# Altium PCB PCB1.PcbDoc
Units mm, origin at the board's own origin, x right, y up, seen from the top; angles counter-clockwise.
Board outline 160 x 100 mm, 4 copper layers (Top Signal, GND, Power Plane, Bottom Signal), stack 1.538 mm thick; 136 components, 81 nets, 446 pads, 114 vias.
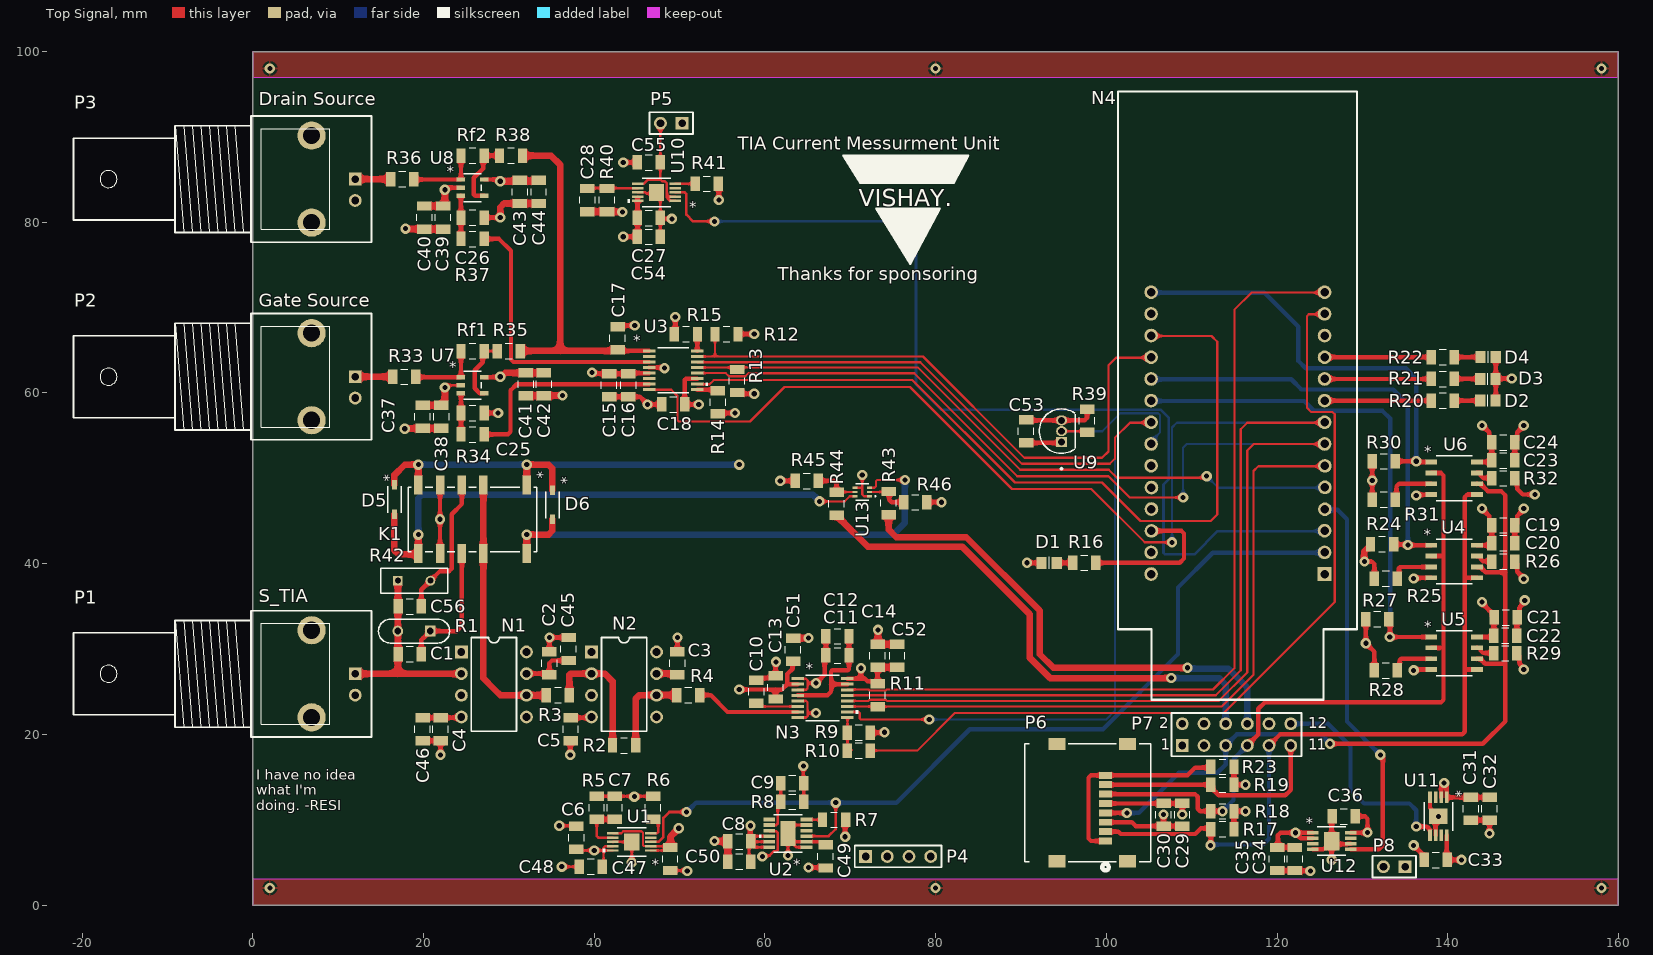
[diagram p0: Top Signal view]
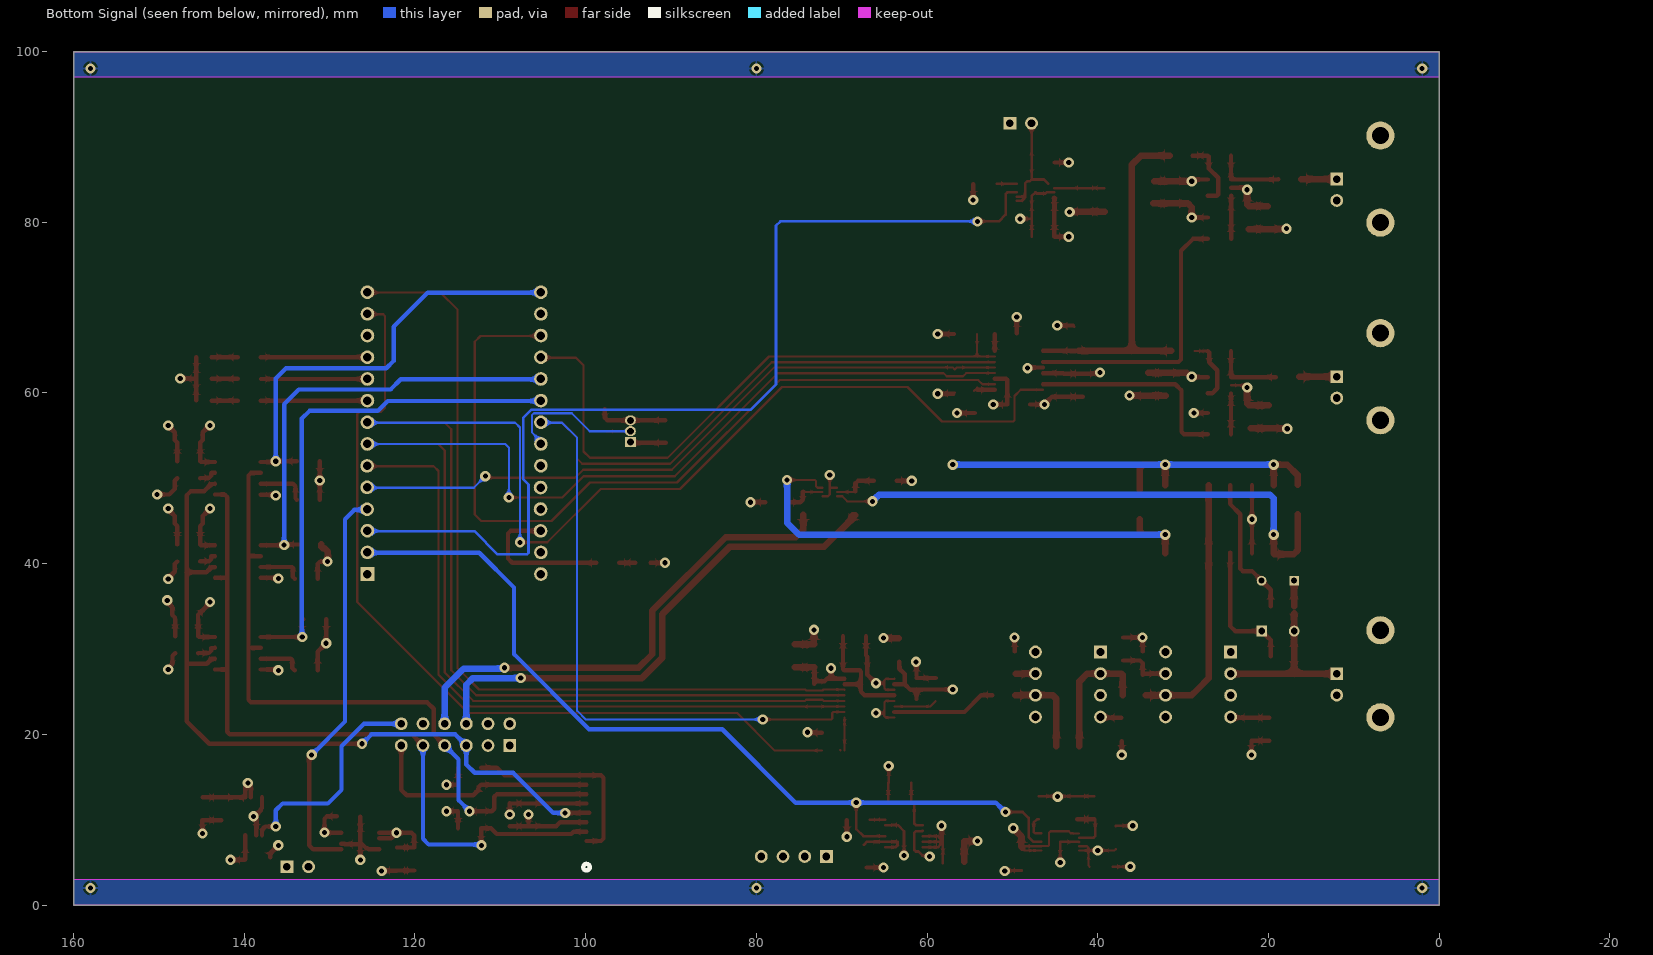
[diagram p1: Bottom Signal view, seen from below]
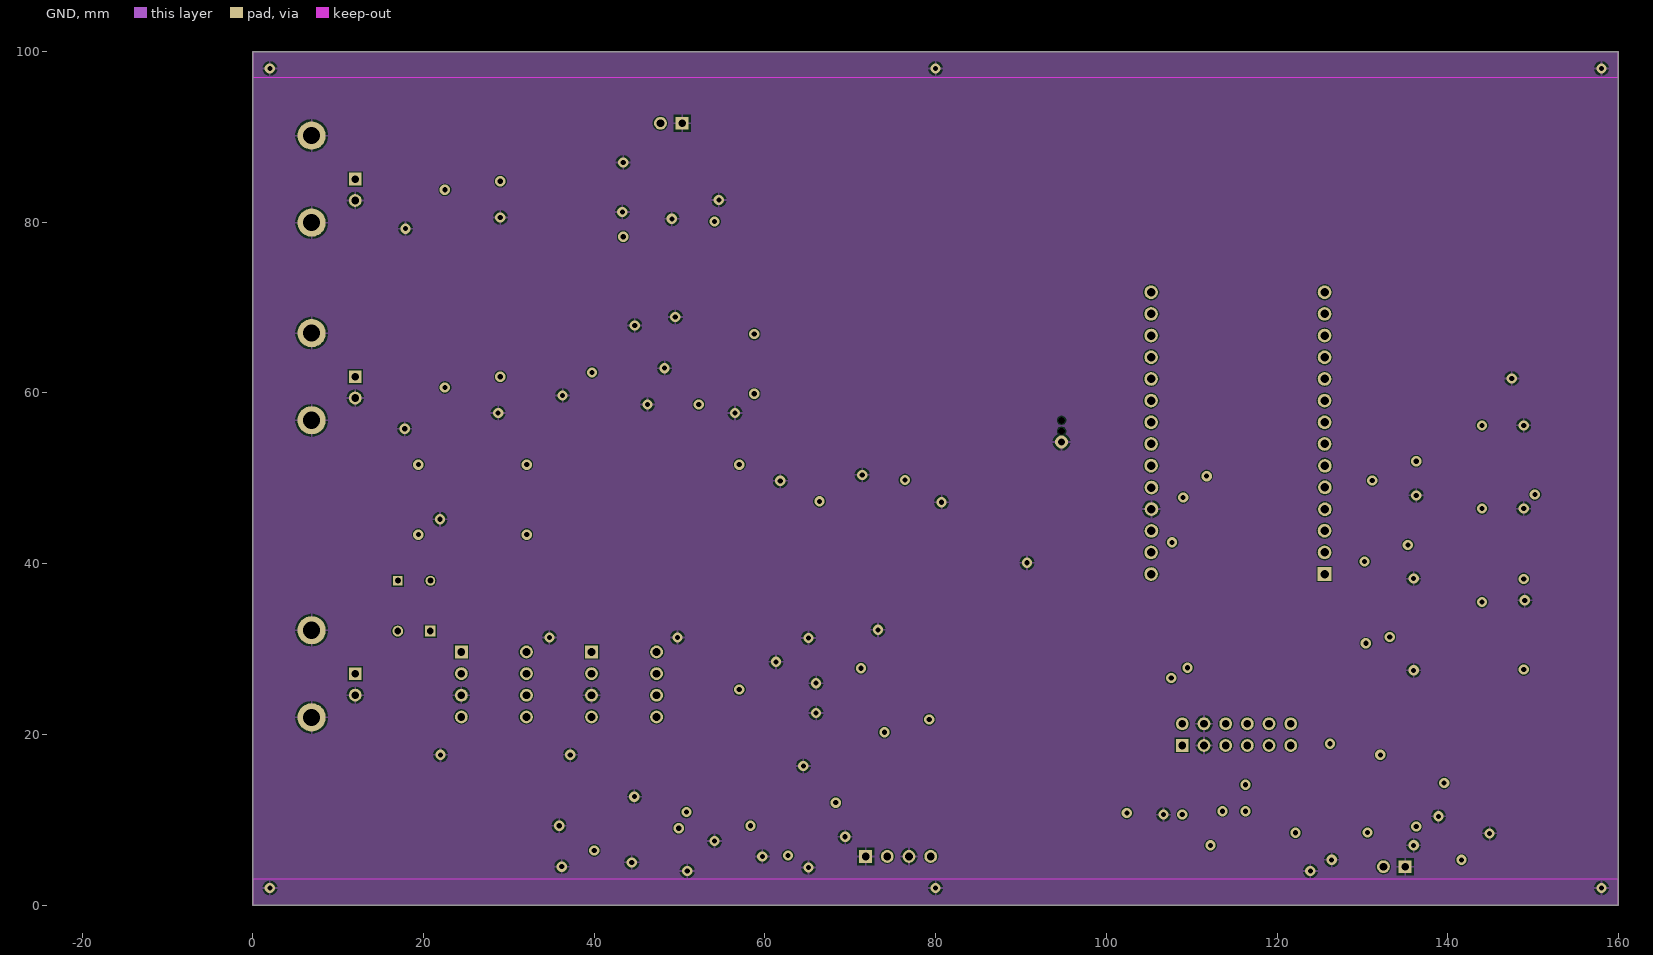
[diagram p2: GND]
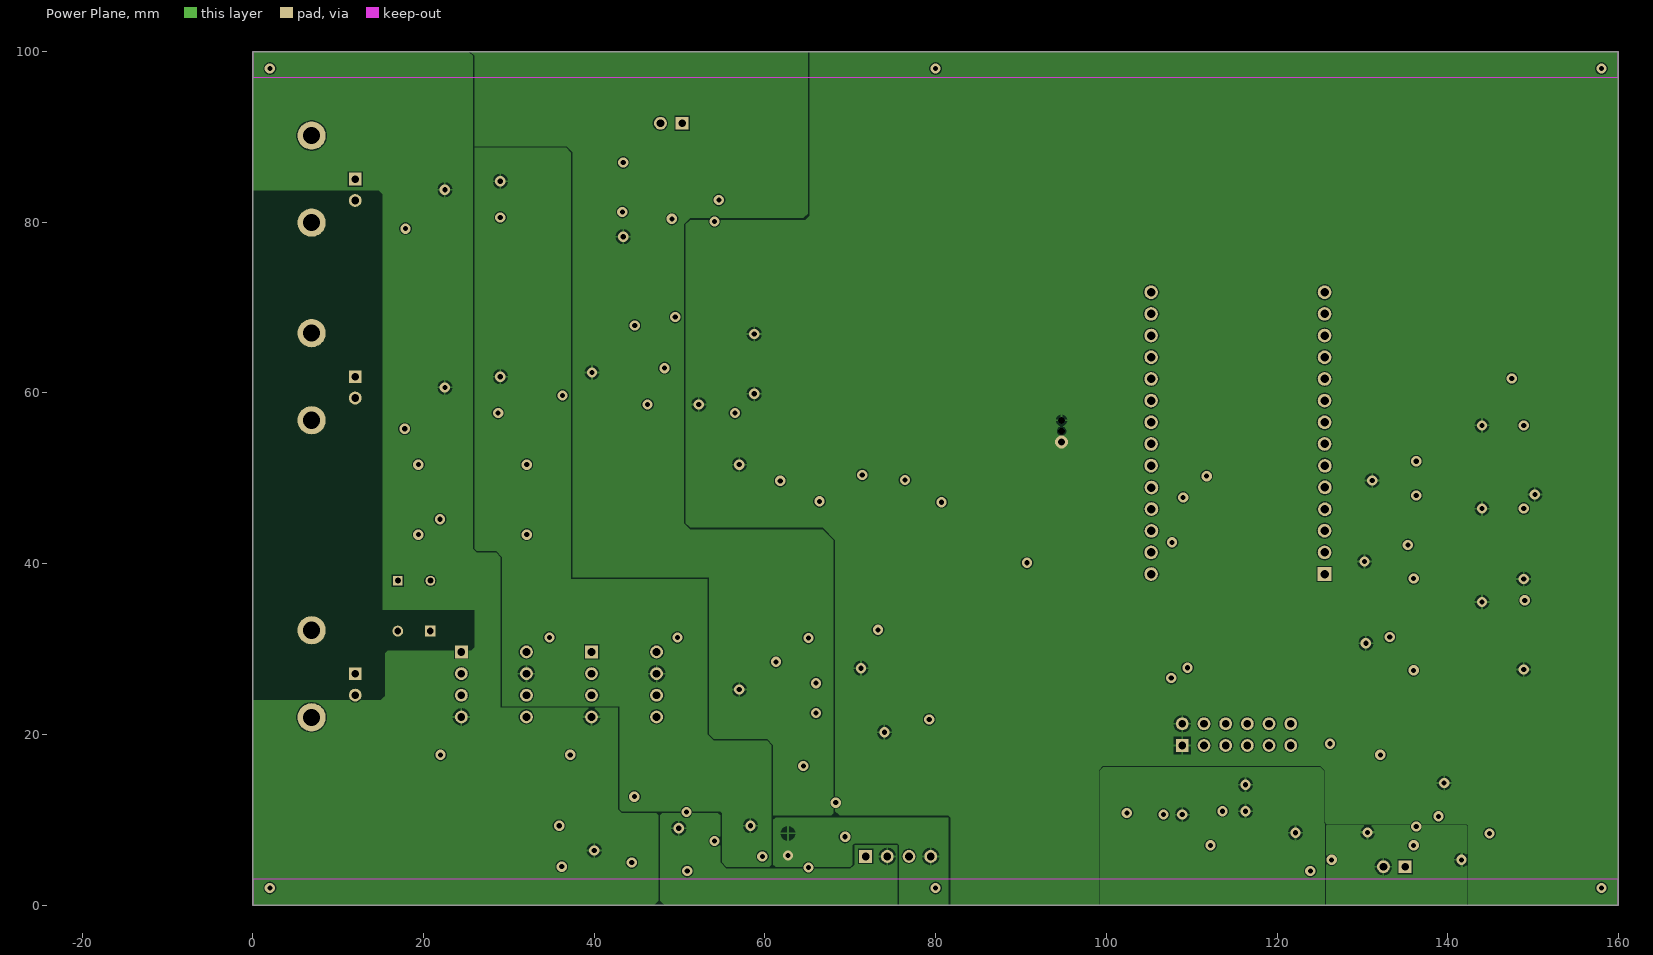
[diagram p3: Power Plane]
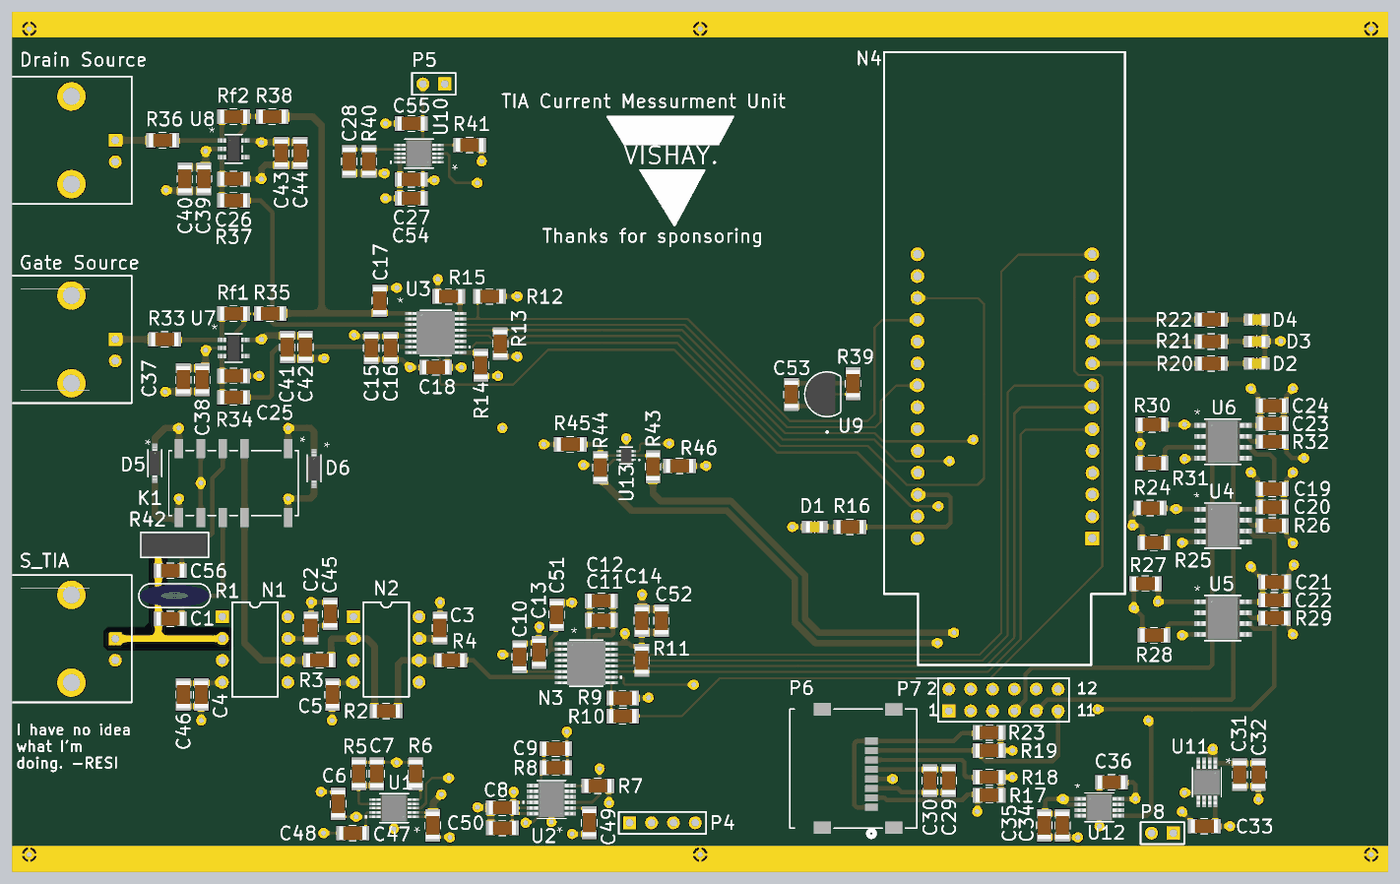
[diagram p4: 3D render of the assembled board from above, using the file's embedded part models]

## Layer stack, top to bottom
Top Solder: solder mask 0.0102, Solder Resist, Dk 3.5
Top Signal: signal copper 0.0356
Dielectric 4: prepreg 0.1524, PP-006, Dk 4.4
GND: signal copper 0.035
Dielectric 1: dielectric 1.0922, FR-4, Dk 4.8
Power Plane: signal copper 0.035
Dielectric 5: prepreg 0.1524, PP-006, Dk 4.4
Bottom Signal: signal copper 0.0356
Bottom Solder: solder mask 0.0102, Solder Resist, Dk 3.5

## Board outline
0,0 160,0 160,100 0,100

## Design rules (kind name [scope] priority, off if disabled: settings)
Clearance [All] p1: gap=0.127 ignorepadtopadclearanceinfootprint=TRUE except(0.025: THPad-THPad)
MinimumSolderMaskSliver THT_21-0248A_Q3-1_MXM [HasFootprint('21-0248A_Q3-1_MXM')] p1: minsoldermaskwidth=0
MinimumSolderMaskSliver [All] p2: minsoldermaskwidth=0.127
PolygonConnect [All] p1: connectstyle=Relief reliefconductorwidth=0.254 reliefentries=4 polygonreliefangle="90 Angle" airgapwidth=0.254
RoutingVias [All] p1: holewidth=0.6 width=1.2 viastyle="Through Hole" minholewidth=0.3 minwidth=0.6 maxholewidth=1 maxwidth=2
SilkToSolderMaskClearance SilkToSolderMaskClearance_1 [HasFootprint('BNC_RA CON')] p1: minsilkscreentomaskgap=0 clearancetoexposedcopper=TRUE
SilkToSolderMaskClearance [IsPad] p2: minsilkscreentomaskgap=0.127 clearancetoexposedcopper=TRUE
SolderMaskExpansion [All] p1: expansion=0.102 istentingtop=FALSE
Width Source [InNet('M_source')] p1: maxlimit=2.54 minlimit=0.254 preferedwidth=0.762
Width Width_1 [All] p2: maxlimit=0.762 minlimit=0.254 preferedwidth=0.762
28 further rules are at their usual default settings.

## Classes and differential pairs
component class U_Digital_Psu: C31 C32 C33 C34 C35 C36 U11 U12
component class U_Analog_PSU_5: C27 C28 C54 R40 R41 U10
component class U_Temp_Sensors: C53 R39 U9
component class U_Source_TIA: C1 C2 C3 C4 C5 C45 C46 C56 D5 D6 K1 N1 N2 R1 R2 R3 R4 R42
component class U_PSRAM_SPI: C19 C20 C21 C22 C23 C24 R24 R25 R26 R27 R28 R29 R30 R31 R32 U4 U5 U6
component class U_OPV_psu: C6 C7 C8 C9 C47 C48 C49 C50 R5 R6 R7 R8 U2
component class U_DAC_Buffer_Filter: C25 C26 C37 C38 C39 C40 C41 C42 C43 C44 R33 R34 R35 R36 R37 R38 Rf1 Rf2 U7 U8
component class U_CortexM3_dev: C29 C30 D1 D2 D3 D4 N4 P6 P7 R16 R17 R18 R19 R20 R21 R22 R23
component class U_ADC_8681: C10 C11 C12 C13 C14 C51 C52 N3 R9 R10 R11
component class U_AD_5689_DAC: C15 C16 C17 C18 R12 R13 R14 R15 U3
component class Top_Sheet: C55 P1 P2 P3 P4 P5 P8 R43 R44 R45 R46 U13

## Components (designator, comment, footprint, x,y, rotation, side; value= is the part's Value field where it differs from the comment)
C1 "22pF" C1206-KUE 18.4,29.4 r0 top
C2 "100nF" C1206-KUE 34.75,28.35 r270 top
C3 "100nF" C1206-KUE 49.75,28.35 r270 top
C4 "100nF" C1206-KUE 22,20.6 r90 top
C5 "100nF" C1206-KUE 37.25,20.6 r90 top
C6 "10uF" C1206-KUE 37.907,7.9 r270 top
C7 "4.7uF" C1206-KUE 42.407,11.4 r270 top
C8 "10uF" C1206-KUE 57,7.451 r0 top
C9 "4.7uF" C1206-KUE 63.2,14.3 r180 top
C10 "10uF" C1206-KUE 59,25 r270 top
C11 "100nF" C1206-KUE 68.5,29.25 r0 top
C12 "10uF" C1206-KUE 68.5,31.5 r0 top
C13 "0.1uF" C1206-KUE 61.25,25.5 r270 top
C14 "0.1uF" C1206-KUE 73.2,29.2 r270 top
C15 "10uF" C1206-KUE 41.75,60.9 r90 top
C16 "0.1uF" C1206-KUE 44,60.9 r90 top
C17 "0.1uF" C1206-KUE 42.75,66.4 r270 top
C18 "0.1uF" C1206-KUE 49.25,58.65 r0 top
C19 "1uF" C1206-KUE 146.5,44.5 r180 top
C20 "100nF" C1206-KUE 146.5,42.4 r180 top
C21 "1uF" C1206-KUE 146.775,33.7 r180 top
C22 "100nF" C1206-KUE 146.75,31.575 r180 top
C23 "1uF" C1206-KUE 146.5,52.1 r180 top
C24 "100nF" C1206-KUE 146.5,54.2 r180 top
C25 "1uF" C1206-KUE 25.75,57.65 r180 top
C26 "1uF" C1206-KUE 25.75,80.55 r180 top
C27 "10uF" C1206-KUE 46.4,80.5 r180 top
C28 "4.7uF" C1206-KUE 39.2,82.6 r90 top
C29 "100nF" C1206-KUE 108.9,10.6 r90 top
C30 "1uF" C1206-KUE 106.7,10.6 r90 top
C31 "100nF" C1206-KUE 142.7,11.3 r90 top
C32 "10uF" C1206-KUE 144.9,11.3 r90 top
C33 "10uF" C1206-KUE 138.6,5.3 r0 top
C34 "100nF" C1206-KUE 122.1,5.4 r90 top
C35 "10uF" C1206-KUE 120,5.4 r90 top
C36 "4.7uF" C1206-KUE 127.8,10.4 r0 top
C37 "100nF" C1206-KUE 19.9,57.2 r90 top
C38 "1uF" C1206-KUE 22.1,57.2 r90 top
C39 "100nF" C1206-KUE 22.3,80.55 r90 top
C40 "1uF" C1206-KUE 20.1,80.55 r90 top
C41 "100nF" C1206-KUE 32,61 r90 top
C42 "1uF" C1206-KUE 34.1,61 r90 top
C43 "100nF" C1206-KUE 31.3,83.55 r90 top
C44 "1uF" C1206-KUE 33.5,83.55 r90 top
C45 "10uF" C1206-KUE 37,30 r270 top
C46 "10uF" C1206-KUE 19.9,20.6 r270 top
C47 "10uF" C1206-KUE 48.907,5.4 r90 top
C48 "100nF" C1206-KUE 39.607,4.5 r0 top
C49 "10uF" C1206-KUE 67.1,5.7 r90 top
C50 "100nF" C1206-KUE 57,5.1 r0 top
C51 "10uF" C1206-KUE 63.3,29.9 r270 top
C52 "10uF" C1206-KUE 75.5,29.2 r270 top
C53 "1uF" C1206-KUE 90.6,55.5 r90 top
C54 "100nF" C1206-KUE 46.4,78.3 r180 top
C55 "100nF" C1206-KUE 46.4,87 r0 top
C56 "22pF" C1206-KUE 18.4,35 r0 top
D1 "GREEN" 6-0805_N-KUE 93.3,40.1 r180 top
D2 "GREEN" 6-0805_N-KUE 144.7,59.1 r0 top
D3 "RED" 6-0805_N-KUE 144.7,61.65 r0 top
D4 "RED" 6-0805_N-KUE 144.725,64.2 r0 top
D5 "1N4148W-7" SOD123_DIO 16.6,47.5 r270 top
D6 "1N4148W-7" SOD123_DIO 35.1,46.9 r270 top
K1 "G6SK-2F-TR DC3" "RELAY_G6SK-2F DC3_OMR" 19.4,41.2 r270 top
N1 "LMC6001AIN/NOPB" DIP8 28.25,25.85 r270 top
N2 "LMC6001AIN/NOPB" DIP8 43.5,25.85 r270 top
N3 "ADS8681IPW" PW16_TEX 66.75,24.25 r0 top
N4 "STM32F103" DIP28 129.375,24.05 r180 top
P1 "BNC" "BNC_RA CON" 12,27.1 r0 top
P2 "BNC" "BNC_RA CON" 12,61.9 r0 top
P3 "BNC" "BNC_RA CON" 12,85.05 r0 top
P4 "Header 4" HDR1X4 71.8,5.7 r0 top
P5 "Header 2" HDR1X2 50.3,91.6 r180 top
P6 "472192001" CONN_47219-2001_MOL 97.8,12 r90 top
P7 "Header 6X2" HDR2X6 108.9,18.7 r0 top
P8 "Header 2" HDR1X2 135,4.5 r180 top
R1 "CNS020-10MP" RES_CNS020_VIS 20.8,32.1 r180 top
R2 "10k" C1206-KUE 43.5,18.7 r180 top
R3 "33k" C1206-KUE 35.75,24.6 r180 top
R4 "10" C1206-KUE 51,24.6 r180 top
R5 "78.7k" C1206-KUE 40.3,11.4 r90 top
R6 "0" C1206-KUE 46.907,11.4 r90 top
R7 "0" C1206-KUE 68.1,10 r0 top
R8 "78.7k" C1206-KUE 63.2,12.1 r0 top
R9 "10k" C1206-KUE 71,20.2 r180 top
R10 "1k" C1206-KUE 71,18.1 r180 top
R11 "4.7k" C1206-KUE 73.2,24.6 r270 top
R12 "4.7k" C1206-KUE 55.5,66.9 r180 top
R13 "4.7k" C1206-KUE 56.75,61.4 r90 top
R14 "10k" C1206-KUE 54.5,58.9 r270 top
R15 "10k" C1206-KUE 50.75,66.9 r180 top
R16 "3.9k" C1206-KUE 97.4,40.1 r180 top
R17 "4.7k" C1206-KUE 113.6,8.9 r180 top
R18 "4.7k" C1206-KUE 113.6,11 r180 top
R19 "4.7k" C1206-KUE 113.6,14.1 r180 top
R20 "3.9k" C1206-KUE 139.4,59.1 r0 top
R21 "2.7k" C1206-KUE 139.4,61.65 r0 top
R22 "2.7k" C1206-KUE 139.4,64.2 r0 top
R23 "4.7k" C1206-KUE 113.6,16.2 r0 top
R24 "4.7k" C1206-KUE 132.3,42.3 r0 top
R25 "10k" C1206-KUE 132.75,38.25 r0 top
R26 "10k" C1206-KUE 146.5,40.25 r180 top
R27 "4.7k" C1206-KUE 131.75,33.5 r0 top
R28 "10k" C1206-KUE 132.75,27.5 r0 top
R29 "10k" C1206-KUE 146.75,29.5 r180 top
R30 "4.7k" C1206-KUE 132.5,52 r0 top
R31 "10k" C1206-KUE 132.5,47.5 r0 top
R32 "10k" C1206-KUE 146.5,50 r180 top
R33 "100" C1206-KUE 17.75,61.9 r180 top
R34 "10k" C1206-KUE 25.75,55.15 r180 top
R35 "10k" C1206-KUE 30,64.9 r180 top
R36 "100" C1206-KUE 17.5,85.05 r180 top
R37 "10k" C1206-KUE 25.75,78.05 r180 top
R38 "10k" C1206-KUE 30.25,87.8 r180 top
R39 "4.7k" C1206-KUE 97.75,56.75 r270 top
R40 "49.9k" C1206-KUE 41.5,82.6 r270 top
R41 "0" C1206-KUE 53.2,84.5 r0 top
R42 "Y0062100K000T9L" RES_S102K_7P62X2P67_VIS 17,38 r0 top
R43 "1k" C1206-KUE 74.5,47.1 r270 top
R44 "1k" C1206-KUE 68.4,47 r270 top
R45 "10k" C1206-KUE 64.9,49.7 r180 top
R46 "10k" C1206-KUE 77.6,47.2 r0 top
Rf1 "20k" C1206-KUE 25.75,64.9 r180 top
Rf2 "20k" C1206-KUE 25.75,87.8 r180 top
U1 "LT3042EMSE#TRPBF" 05-08-1664_ADI 44.407,7.4 r180 top
U2 "LT3094EMSE#TRPBF" MSE_05-08-1666_ADI 62.7,8.4 r180 top
U3 "AD5689RBRUZ" RU_16_ADI 49.25,62.65 r0 top
U4 "APS6404L-3SQR-SN" APS6404L-3SQR-SN_APY 140.75,40.25 r0 top
U5 "APS6404L-3SQR-SN" APS6404L-3SQR-SN_APY 140.75,29.5 r0 top
U6 "APS6404L-3SQR-SN" APS6404L-3SQR-SN_APY 140.75,50 r0 top
U7 "OPA197IDBVR" DBV5_TEX 25.75,60.9 r0 top
U8 "OPA197IDBVR" DBV5_TEX 25.75,84.05 r0 top
U9 "DS18B20+" 21-0248A_Q3-1_MXM 94.75,54.25 r90 top
U10 "LT3042EMSE#TRPBF" 05-08-1664_ADI 47.3,83.5 r180 top
U11 "TLV76733DGNR" VSSOP8_DGN_TEX 138.9,10.4 r270 top
U12 "TLV76733DGNR" VSSOP8_DGN_TEX 126.4,7.5 r0 top
U13 "DMC2400UV-7" SON_400UV-7_DIO 71.4,48.4 r180 top

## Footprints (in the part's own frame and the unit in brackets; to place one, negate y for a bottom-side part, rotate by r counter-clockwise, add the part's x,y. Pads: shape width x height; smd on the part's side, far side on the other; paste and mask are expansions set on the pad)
05-08-1664_ADI [mil]
  rect 52.28x11 smd paste+0 mask+0: 1(-87.14,39.37) 2(-87.14,19.69) 3(-87.14,0) 4(-87.14,-19.68) 5(-87.14,-39.37) 6(87.14,-39.37) 7(87.14,-19.68) 8(87.14,0) 9(87.14,19.69) 10(87.14,39.37)
  rect 70x78 smd paste+0 mask+0: 11(0,0)
  silkscreen extent -66,-66 133,66, body extent -99,-61 99,61, height 43
6-0805_N-KUE [mm] "Chip Resistor, Body 2.0x1.2mm, IPC Medium Density"
  rect 1.2x1.4 smd: 1(-0.9,0) 2(0.9,0)
  silkscreen extent 0,-0.69 0,0.69, body extent -1,-0.63 1,0.63, height 0.8
21-0248A_Q3-1_MXM [mm]
  rect 1.168x1.27 / inner round 1.524 / far side rect 1.168x1.27 hole 0.8 paste-0.635 mask+0: 1(0,0)
  oval 1.168x1.27 / inner round 0 / far side oval 1.168x1.27 hole 0.8 paste-0.635 mask+0: 2(1.27,0) 3(2.54,0)
  silkscreen extent -3.24,-1.59 3.87,2.6, body extent -1.21,-0.95 3.75,2.48, height 4.95
APS6404L-3SQR-SN_APY [mm]
  rect 1.356x0.558 smd paste+0 mask+0: 1(-2.672,1.905) 2(-2.672,0.635) 3(-2.672,-0.635) 4(-2.672,-1.905) 5(2.672,-1.905) 6(2.672,-0.635) 7(2.672,0.635) 8(2.672,1.905)
  silkscreen extent -2.12,-2.63 2.12,2.63, body extent -3,-2.5 3,2.5, height 1.76
"BNC_RA CON" [mm] "Connector; BNC Elbow"
  rect 1.5x1.5 hole 0.9: 1(0,0)
  round 3.3 hole 2: 2(-5.1,-5.1) 2(-5.1,5.1)
  round 1.5 hole 0.9: 2(0,-2.5)
  silkscreen extent -33,-7.4 1.9,7.4
C1206-KUE [mm] "Chip Capacitor, Body 3.2x1.6mm, IPC High Density"
  rect 1.1x1.7 smd: 1(-1.35,0) 2(1.35,0)
  silkscreen extent -0.4,-0.9 0.4,0.9, body extent -1.6,-0.8 1.6,0.8, height 0.95
CONN_47219-2001_MOL [mil]
  rect 32x59 smd paste+0 mask+0: 1(126.18,-82.61) 2(82.87,-82.61) 3(39.57,-82.61) 4(-3.74,-82.61) 5(-47.05,-82.61) 6(-90.35,-82.61) 7(-133.66,-82.61) 8(-176.97,-82.61)
  rect 57x79 smd paste-39.5 mask-39.5: G1(270.67,-184.97) G2(270.67,141.8) G3(-270.67,141.8) G4(-270.67,-184.97)
  silkscreen extent -312,-290 272,290
DBV5_TEX [mil]
  rect 38.5x20 smd paste+0 mask+0: 1(-53.75,37.4) 2(-53.75,0) 3(-53.75,-37.4) 4(53.75,-37.4) 5(53.75,37.4)
  silkscreen extent -40,-65 39,65, body extent -59,-60 59,60, height 57
DIP8 [mm] "DIP; 8 Leads; Row Spacing 7.62 mm; Pitch 2.54 mm"
  rect 1.5x1.5 hole 0.9: 1(-3.81,-3.81)
  round 1.5 hole 0.9: 2(-1.27,-3.81) 3(1.27,-3.81) 4(3.81,-3.81) 5(3.81,3.81) 6(1.27,3.81) 7(-1.27,3.81) 8(-3.81,3.81)
  silkscreen extent -5.5,-2.65 5.5,2.65
DIP28 [mm]
  rect 1.6x1.6 hole 1: 1(3.81,-14.732)
  round 1.6 hole 1: 2(3.81,-17.272) 3(3.81,-19.812) 4(3.772,-22.328) 5(3.772,-24.889) 6(3.772,-27.408) 7(3.81,-29.972) 8(3.81,-32.512) 9(3.81,-35.052) 10(3.81,-37.592) 11(3.81,-40.132) 12(3.81,-42.672) 13(3.81,-45.212) 14(3.81,-47.752) 15(24.13,-14.732) 16(24.13,-17.272) 17(24.092,-19.788) 18(24.092,-22.349) 19(24.092,-24.868) 20(24.13,-27.432) 21(24.13,-29.972) 22(24.13,-32.512) 23(24.13,-35.052) 24(24.13,-37.592) 25(24.13,-40.132) 26(24.13,-42.672) 27(24.13,-45.212) 28(24.13,-47.752)
  silkscreen extent 0,-71.26 28,0
HDR1X2 [mm] "Connector; Header; 2 Position"
  rect 1.5x1.5 hole 0.9: 1(0,0)
  round 1.5 hole 0.9: 2(2.54,0)
  silkscreen extent -1.27,-1.27 3.81,1.27
HDR1X4 [mm] "Connector; Header; 4 Position"
  rect 1.5x1.5 hole 0.9: 1(0,0)
  round 1.5 hole 0.9: 2(2.54,0) 3(5.08,0) 4(7.62,0)
  silkscreen extent -1.27,-1.27 8.89,1.27
HDR2X6 [mm] "Connector; Header; 6x2 Position"
  rect 1.5x1.5 hole 0.9: 1(0,0)
  round 1.5 hole 0.9: 2(0,2.54) 3(2.54,0) 4(2.54,2.54) 5(5.08,0) 6(5.08,2.54) 7(7.62,0) 8(7.62,2.54) 9(10.16,0) 10(10.16,2.54) 11(12.7,0) 12(12.7,2.54)
  silkscreen extent -1.27,-1.27 13.97,3.81
MSE_05-08-1666_ADI [mil]
  rect 54.56x16.97 smd paste+0 mask+0: 1(-86,63.98) 2(-86,38.39) 3(-86,12.8) 4(-86,-12.8) 5(-86,-38.39) 6(-86,-63.98) 7(86,-63.98) 8(86,-38.39) 9(86,-12.8) 10(86,12.8) 11(86,38.39) 12(86,63.98)
  rect 69x116 smd paste-57.5 mask+0: 13(0,0)
  silkscreen extent -66,-87 133,87, body extent -99,-81 99,81, height 43
PW16_TEX [mil]
  rect 58x14 smd paste+0 mask+0: 1(-115,89.57) 2(-115,63.98) 3(-115,38.39) 4(-115,12.79) 5(-115,-12.8) 6(-115,-38.39) 7(-115,-63.98) 8(-115,-89.57) 9(115,-89.57) 10(115,-63.98) 11(115,-38.39) 12(115,-12.8) 13(115,12.79) 14(115,38.39) 15(115,63.98) 16(115,89.57)
  silkscreen extent -76,-105 164,106, body extent -130,-101 130,101, height 47
"RELAY_G6SK-2F DC3_OMR" [mil]
  rect 87x39 smd paste+0 mask+0: 1(-314.96,500) 3(-314.96,300) 4(-314.96,200) 5(-314.96,100) 6(-314.96,0) 7(0,0) 8(0,100) 9(0,200) 10(0,300) 12(0,500)
  silkscreen extent -306,-46 -9,546
RES_CNS020_VIS [mm]
  rect 1.27x1.27 hole 0.8 paste-0.635 mask+0: 1(0,0)
  round 1.27 hole 0.8 paste-0.635 mask+0: 2(3.81,0)
  silkscreen extent -2.26,-1.4 6.07,1.4, body extent -2.13,-1.27 5.94,1.27, height 6.6
RES_S102K_7P62X2P67_VIS [mil]
  rect 45x45 hole 27.56 paste-22.5 mask+0: 1(0,0)
  round 45 hole 27.56 paste-22.5 mask+0: 2(150,0)
  silkscreen extent -80,-58 230,58, body extent -75,-53 225,53, height 336
RU_16_ADI [mm]
  rect 1.461x0.351 smd paste+0 mask+0: 1(-2.825,2.275) 2(-2.825,1.625) 3(-2.825,0.975) 4(-2.825,0.325) 5(-2.825,-0.325) 6(-2.825,-0.975) 7(-2.825,-1.625) 8(-2.825,-2.275) 9(2.825,-2.275) 10(2.825,-1.625) 11(2.825,-0.975) 12(2.825,-0.325) 13(2.825,0.325) 14(2.825,0.975) 15(2.825,1.625) 16(2.825,2.275)
  silkscreen extent -1.81,-2.63 4.06,2.63, body extent -3.2,-2.5 3.2,2.5, height 1.2
SOD123_DIO [mm]
  rect 1.111x0.601 smd paste+0 mask+0: 1(-1.725,0) 2(1.725,0)
  silkscreen extent -1.55,-0.8 1.55,0.8, body extent -1.92,-0.67 1.92,0.67, height 0.81
SON_400UV-7_DIO [mil]
  rect 24x10 smd paste+0 mask+0: 1(-33.5,19.68) 2(-33.5,0) 3(-33.5,-19.69) 4(33.5,-19.69) 5(33.5,0) 6(33.5,19.68)
  silkscreen extent -62,-39 30,39, body extent -34,-34 34,34, height 24
VSSOP8_DGN_TEX [mil]
  rect 52.5x17 smd paste+0 mask+0: 1(-87.25,38.39) 2(-87.25,12.8) 3(-87.25,-12.8) 4(-87.25,-38.38) 5(87.25,-38.38) 6(87.25,-12.8) 7(87.25,12.8) 8(87.25,38.39)
  rect 73x85 smd paste+0 mask+0: EPAD(0,0)
  silkscreen extent -66,-66 66,66, body extent -99,-61 99,61, height 43

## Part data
C1 C2 C3 C4 C5 C6 C7 C8 C9 C10 C11 C12 C13 C14 C15 C16 C17 C18 C19 C20 C21 C22 C23 C24 C25 C26 C27 C28 C29 C30 C31 C32 C33 C34 C35 C36 C37 C38 C39 C40 C41 C42 C43 C44 C45 C46 C47 C48 C49 C50 C51 C52 C53 C54 C55 C56: library part Capacitor, "Capacitor", Manufacturer=Kemet
D1 D2 D3 D4: library part LED0, "Typical INFRARED GaAs LED"
D5 D6 U13: "Description", Manufacturer_Name="Diodes Inc"
K1: "Description", Manufacturer_Name=Omron
N1 N2: library part LMC6001AINNOPB, "Ultra-Low Input Current Amplifier 8-PDIP -40 to 85", Manufacturer=NationalSemiconductor, Manufacturer_Name="Texas Instruments", PartNumber=LMC6001AIN
N3: "16-bit, 1MSPS 1-ch SAR ADC with programmable (Â±12V, Â±10V, Â±6V, Â±5V, Â±2.5V) input ranges on 5V supply 16-TSSOP -40 to 125", Manufacturer_Name="Texas Instruments"
P1 P2 P3: "BNC Elbow Connector"
P4: "Header, 4-Pin"
P5 P8: "Header, 2-Pin"
P6: "1.10mm Pitch microSD Card Connector, Hinge Type, Lead-Free", Manufacturer_Name="Molex Connector Corporation"
P7: "Header, 6-Pin, Dual row"
R1: library part CNS020-10KP, "CNS 020 10K 0,02% e2", Manufacturer_Name=Vishay
R2 R3 R4 R5 R6 R7 R8 R9 R10 R11 R12 R13 R14 R15 R16 R17 R18 R19 R20 R21 R22 R23 R24 R25 R26 R27 R28 R29 R30 R31 R32 R33 R34 R35 R36 R37 R38 R39 R40 R41 R43 R44 R45 R46 Rf1 Rf2: library part ResistorSMD, "Resistor SMD", Manufacturer=AVX
R42: "No Description Available", Manufacturer_Name=Vishay
U1 U10: library part LT3042EMSETRPBF, "20V, 200mA, Ultralow Noise, Ultrahigh PSRR RF Linear Regulator", Manufacturer_Name="Analog Devices Inc"
U2: library part LT3094EMSETRPBF, "âˆ’20V, 500mA, Ultralow Noise, Ultrahigh PSRR Negative Linear Regulator", Manufacturer_Name="Analog Devices Inc"
U3: "Dual, 16-Bit nanoDAC+ with 2 ppm/Â°C Reference, SPI Interface", Manufacturer_Name="Analog Devices Inc"
U4 U5 U6: "Description", Manufacturer_Name="AP Memory"
U7 U8: "Single, 36-V, precision, rail-to-rail input output, low offset voltage op amp 5-SOT-23 -40 to 125", Manufacturer_Name="Texas Instruments"
U9: "Programmable Resolution 1-Wire Digital Thermometer", Manufacturer_Name="Analog Devices Inc"
U11 U12: "Adjustable- and fixed-output, 1-A, 16-V, positive-voltage low-dropout (LDO) linear regulator 8-HVSSOP -40 to 125", Manufacturer_Name="Texas Instruments"

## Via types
v1: diameter 1.2, hole 0.6, Top Signal to Bottom Signal, 114 vias

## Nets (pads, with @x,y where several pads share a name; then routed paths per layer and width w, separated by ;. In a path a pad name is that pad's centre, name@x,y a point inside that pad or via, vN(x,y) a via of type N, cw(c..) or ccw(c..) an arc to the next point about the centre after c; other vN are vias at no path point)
AVDD: C13.2 C15.2 C16.2 C27.2 C51.2 C54.2 N3.2 U3.5 U10.9 U10.10 | length 24.1
  Top Signal w0.254: v1(39.75,62.4) v1@39.9,62.25 ; C16.2 C16.2@44.075,62.325
  Top Signal w0.508: v1@39.9,62.25 C15.2 C16.2 ; v1(43.4,78.3) C54.2 ; C16.2@44.075,62.325 U3.5 ; C54.2@45.087,78.337 U10.10 U10.9@45.087,82.9 ; v1(57,25.25) 61.25,25.25 ; C13.2 61.25,25.25 ; C51.2@63.25,28.5 63.25,27.7 62.625,27.075 62.625,25.875 ; N3.2 62.625,25.875 ; 61.25,25.25 62,25.25 62.625,25.875
damper_out: N2.6 R2.1 R4.2 | length 10.6
  Top Signal w0.254: N2.6 N2.6@47.33,24.6
  Top Signal w0.762: R2.1@44.85,18.6 44.85,24.154 45.296,24.6 47.29,24.6 N2.6 ; N2.6@47.33,24.6 R4.2
DVDD: C14.2 C18.2 C19.2 C20.2 C21.2 C22.2 C23.2 C24.2 C31.2 C32.2 C52.2 C53.2 D5.1 D6.1 K1.1 K1.6 N3.16 P7.1 P7.2 R9.1 R11.1 R12.1 R13.1 R24.1 R25.1 R26.1 R27.1 R28.1 R29.1 R30.1 R31.1 R32.1 R39.1 U3.11 U4.8 U5.8 U6.8 U9.3 U11.1 U11.2 | length 133.8
  Top Signal w0.254: R13.1 R13.1@56.9,59.9 ; v1@73.95,20.2 v1(74,20.25)
  Top Signal w0.508: U3.11 50.749,61.675 50.6,61.526 C18.2 v1(52.25,58.65) ; R12.1 v1(58.75,66.9) ; R13.1@56.9,59.9 v1(58.75,59.9) ; N3.16 71.25,26.525 ; v1(71.25,27.75) 71.25,26.525 ; R9.1 v1@73.95,20.2 ; R11.1@73.018,26.132 72.919,26.231 72.019,26.231 71.725,26.525 71.25,26.525 ; R11.1 C14.2 ; C53.2@90.66,56.79 U9.3 97.452,56.79 97.75,57.088 R39.1 ; v1(130.25,40.25) 131.102,40.25 131.4,39.952 R25.1 ; R27.1 v1(130.4,30.671) 131.4,29.671 R28.1 ; R31.1 v1(131.15,49.75) R30.1 ; U11.2 139.225,13.948 v1(139.577,14.3) 139.875,14.002 U11.1 C32.2@144.866,12.616 ; U5.8 145.305,31.405 145.4,31.5 C22.2 C21.2@145.4,33.5 ; U4.8 145.055,42.155 145.15,42.25 C20.2 C19.2@145.15,44.25 ; U6.8 145.055,51.905 145.15,52 C23.2 C24.2@145.15,54 ; v1(144,35.5) 144,35.4 145.104,34.296 145.129,34.296 145.425,34 C21.2 ; v1(144,46.45) 144,46.444 144.854,45.59 144.854,44.696 C19.2@145.15,44.4 ; v1(144,56.2) 144.044,56.2 144.854,55.39 144.854,54.496 C24.2 ; R26.1 148.146,39.954 148.146,39.06 148.9,38.306 v1(148.9,38.2) ; R32.1 148.146,49.704 148.146,48.744 148.79,48.1 v1(150.2,48.1) ; R29.1 148.396,29.204 148.396,28.31 148.768,27.939 148.768,27.732 v1(148.9,27.6)
  Top Signal w0.762: D5.1 16.6,50.4 17.8,51.6 v1(19.4,51.6) K1.6 ; K1.1 v1(32.1,51.6) 34.654,51.6 35.1,51.154 D6.1 ; C14.2 C52.2 ; v1(130.25,40.25) 130.2,40.3 130.2,41.4 130.631,41.831 130.781,41.831 130.95,42 R24.1
  Bottom Signal w0.762: v1(19.4,51.6) v1(32.1,51.6) v1(57,51.6)
DVDD_SD: C29.2 C30.2 C34.2 C35.2 P6.4 R17.1 R18.1 R19.1 R23.2 U12.1 U12.2 | length 26.9
  Top Signal w0.508: P6.4 C29.2@108.855,11.905 ; v1(108.9,10.6) C29.2 ; R17.1@114.95,9 R18.1 v1(116.3,11) ; R23.2@114.95,16.1 R19.1 v1(116.3,14.1) ; C34.2 120.1,6.75 120.1,8.177 120.398,8.475 v1(122.153,8.475) U12.1 ; v1@122.153,8.453 122.781,7.825 U12.2
GND: C2.1 C3.1 C4.1 C5.1 C6.1 C7.1 C8.1 C9.1 C10.1 C11.1 C12.1 C13.1 C14.1 C15.1 C16.1 C17.1 C18.1 C19.1 C20.1 C21.1 C22.1 C23.1 C24.1 C25.1 C26.1 C27.1 C28.1 C29.1 C30.1 C31.1 C32.1 C33.1 C34.1 C35.1 C36.1 C37.1 C38.1 C39.1 C40.1 C41.1 C42.1 C43.1 C44.1 C45.1 C46.2 C47.1 C48.1 C49.1 C50.1 C51.1 C52.1 C53.1 C54.1 C55.1 D1.2 D2.2 D3.2 D4.2 K1.5 K1.8 N1.3 N2.3 N3.1 N3.3 N3.5 N3.8 N4.18 P1.2 P2.2 P3.2 P4.1 P4.3 P5.1 P6.6 P7.3 P7.4 P8.1 R5.2 R6.2 R7.2 R8.2 R14.2 R15.2 R40.2 R41.2 R45.2 R46.2 U1.8 U1.11 U2.9 U3.4 U4.4 U5.4 U6.4 U9.1 U10.8 U10.11 U11.4 U11.6 U11.EPAD U12.4 U12.6 U12.EPAD U13.1 U13.4 | length 207.9
  Top Signal w0.254: C17.1 C17.1@42.9,67.9 ; C18.1 C18.1@48,58.75 ; R15.2 R15.2@49.5,67 ; R14.2@54.4,57.65 R14.2 ; N3.1@63.804,26.55 63.854,26.5 64.851,26.5 65,26.352 65,26 ; N3.8 64.851,21.975 65,22.124 65,22.5 ; N3.5 64.851,23.925 65,23.776 65,22.5 ; N3.3 64.851,25.225 65,25.374 65,26 ; v1(66,22.5) 65,22.5 ; v1(66,26) 65,26 ; U13.4 71.251,48.9 ; v1(71.4,50.4) 71.4,48.1 71.6,47.9 U13.1
  Top Signal w0.305: v1(35.9,9.3) 37.857,9.3 C6.1 ; v1(36.2,4.5) C48.1 ; R5.2@40.407,12.75 44.657,12.75 v1(44.707,12.7) 44.757,12.75 R6.2 ; U1.8@42.206,7.387 42.219,7.4 U1.11 44.407,5.007 v1(44.4,5) ; U10.8 46,83.5 46.132,83.368 47.168,83.368 U10.11 47.75,83.05 C27.1 ; C54.1 C27.1 ; C47.1 50.85,4.05 v1(50.9,4) ; v1(49.1,80.4) 47.85,80.4 C27.1 ; v1(59.7,5.7) 59.793,5.793 60.542,5.793 61.029,6.28 61.324,6.28 61.488,6.444 61.488,8.483 61.309,8.662 60.579,8.662 U2.9 ; v1(64.5,16.3) 64.5,14.35 C9.1 R8.2 ; C49.1@67.05,4.4 C49.1 ; R7.2@69.4,9.95 R7.2
  Top Signal w0.508: C46.2 C4.1 v1(22,17.6) ; K1.8 K1.5 ; C25.1 v1(28.75,57.65) ; C26.1 v1(29,80.55) ; C2.1 v1(34.75,31.35) C45.1 ; v1(37.2,17.6) C5.1@37.2,19.2 ; C15.1 C16.1 45.35,59.55 v1(46.25,58.65) C18.1 ; C17.1@42.9,67.9 v1(44.75,67.9) ; v1(43.4,87) C55.1 ; U3.4 v1@47.675,62.975 ; R15.2@49.5,67 v1(49.5,68.9) ; C3.1 v1(49.75,31.35) ; R14.2@54.4,57.65 v1(56.5,57.65) ; v1(54.6,82.6) R41.2@54.6,84.45 ; C10.1@59,26.6 C13.1@61.25,26.6 ; C13.1 61.25,28.45 v1(61.3,28.5) ; v1(61.8,49.7) R45.2 ; v1(65.1,4.4) C49.1@67.05,4.4 ; v1(66,26) 67,27 67,29.1 C11.1 C12.1 ; v1(69.4,8) R7.2@69.4,9.95 ; C14.1 C14.1@73.2,30.6 ; R46.2 v1(80.7,47.2) ; C53.1 U9.1@94.65,54.15 ; v1(90.7,40.1) D1.2 ; P6.6 102.995,9.705 103.45,9.25 C30.1 ; v1(106.7,10.6) C30.1 ; C29.1 C30.1 ; C35.1@120.1,4.05 C34.1 122.125,4.025 123.875,4.025 v1(123.9,4) ; U12.4 125.425,6.525 125.575,6.675 125.727,6.675 U12.EPAD@126.4,7.348 ; v1(126.4,5.3) U12.EPAD@126.4,7.137 ; C36.1@126.4,10.35 U12.EPAD U12.EPAD@126.4,7.137 ; U12.6 128.242,7.175 128.203,7.137 U12.EPAD@126.4,7.137 ; v1(136,7) 136.954,6.046 C33.1@136.954,5.596 ; v1(136,27.5) 136.095,27.595 U5.4 ; v1(136,38.25) 136.095,38.345 U4.4 ; v1(136.306,48) 136.376,48.07 138.053,48.07 U6.4 ; U11.4 137.925,11.375 138.074,11.225 138.074,11.073 138.748,10.4 v1(138.9,10.4) ; U11.6 U11.EPAD@138.575,10.075 ; C31.1 C32.1 v1(144.9,8.4) ; D3.2 D3.2@145.625,61.675 ; D2.2@145.625,59.125 D3.2@145.625,61.675 ; D4.2 D3.2@145.625,61.675 ; v1(147.5,61.7) 147.475,61.675 D3.2@145.625,61.675 ; C20.1@147.85,42.25 C19.1@147.85,44.25 ; C19.1@147.85,44.4 148.146,44.696 148.146,45.59 148.9,46.344 v1(148.9,46.45) ; C23.1@147.85,52 C24.1@147.85,54 ; C24.1 148.146,54.496 148.146,55.39 148.9,56.144 v1(148.9,56.2) ; C22.1@148.1,31.5 C21.1@148.1,33.5 ; C21.1 148.421,33.996 148.421,34.89 148.893,35.361 148.893,35.568 v1(149.025,35.7)
  Top Signal w0.762: v1(17.8,55.8) 17.85,55.85 C38.1@22,55.85 ; v1@17.95,79.2 C40.1 C39.1 ; C37.1@20,55.85 C38.1 ; v1(29,80.55) 29,81.754 29.446,82.2 C43.1 C44.1 ; C41.1@32.05,59.7 v1(36.3,59.7) ; C28.1 R40.2 ; R40.2@41.525,81.225 v1@43.275,81.225 ; v1(54.1,7.5) 54.124,7.476 C8.1@55.626,7.476 ; C50.1 C8.1 ; C51.1@63.325,31.275 65.075,31.275 v1(65.1,31.3) ; C14.1 C52.1 ; C14.1@73.25,30.6 v1(73.25,32.25)
  other v1: 2,2 80,2 158,2 21.94,45.2 48.25,62.9 17.9,79.25 43.3,81.2 2,98 80,98 158,98
M_source: C1.1 C56.1 N1.2 P1.1 R1.2 R42.1 | length 22.5
  Top Signal w0.254: N1.2@24.42,27.1 N1.2
  Top Signal w0.762: P1.1 17,27.1 ; C56.1@17,34.2 17,27.1 ; C56.1@17,35 R42.1 ; N1.2@24.42,27.1 17,27.1
neg_out: C2.2 C3.2 C8.2 C41.2 C42.2 C43.2 C44.2 C45.2 C50.2 N1.7 N2.7 U2.10 U2.11 U2.12 U7.5 U8.5 | length 33.3
  Top Signal w0.254: v1@28.95,61.85 v1(29,61.9) ; C2.2@34.63,27.12 C2.2 ; C3.2@49.63,27.12 C3.2 C3.2@49.85,27.1
  Top Signal w0.305: C50.2@58.15,4.9 58.15,7.4 C8.2@58.2,7.45 ; C8.2 58.451,7.351 58.451,7.072 58.748,6.775 U2.12 ; C8.2@58.5,7.827 58.748,8.075 U2.10 ; C8.2@58.525,7.425 U2.11
  Top Signal w0.508: U7.5 v1@28.95,61.85 ; U8.5 v1@28.594,85 ; N1.7 C2.2@34.63,27.12 ; C2.2 34.75,28.35 35.05,28.65 C45.2 ; C8.2@58.25,7.5 58.275,7.525 58.275,9.275 v1(58.3,9.3)
  Top Signal w0.762: v1(29,61.9) 29.137,61.9 29.588,62.35 C41.2 C42.2 ; v1(29,84.8) C44.2@33.4,84.8 ; N2.7 C3.2@49.63,27.12
NetC1_2: C1.2 K1.9 R1.1 | length 15.9
  Top Signal w0.508: C1.2@19.75,29.16 C1.2 19.75,31.05 R1.1 23.9,32.1 24.5,32.7 K1.9@24.5,41.3
NetC7_2: C7.2 R5.1 U1.7 | length 5.9
  Top Signal w0.305: R5.1 40.3,8.079 40.479,7.9 U1.7
  Top Signal w0.508: R5.1@40.407,10.05 C7.2
NetC9_2: C9.2 R8.1 U2.8 | length 5.9
  Top Signal w0.305: U2.8 61.321,9.375 61.5,9.554 61.5,11.75 R8.1 C9.2
NetC25_2: C25.2 R34.2 U7.3 | length 4.8
  Top Signal w0.254: U7.3 U7.3@24.4,59.935
  Top Signal w0.508: R34.2 C25.2 U7.3@24.4,59.935
NetC26_2: C26.2 R37.2 U8.3 | length 5.1
  Top Signal w0.254: R37.2@24.385,78.065 R37.2
  Top Signal w0.508: R37.2@24.385,78.065 U8.3
NetC28_2: C28.2 R40.1 U10.7 | length 5.8
  Top Signal w0.305: C28.2@39.25,84 U10.7
NetC33_2: C33.2 C36.2 P8.2 U11.8 U12.8 | length 9.6
  Top Signal w0.508: U12.8 v1@130.575,8.475 ; C36.2 130.302,10.4 130.6,10.102 v1(130.6,8.5) ; C33.2@139.875,5.375 U11.8 ; C33.2 v1(141.6,5.3)
NetC47_2: C47.2 P4.2 U1.1 U1.2 U1.6 | length 13.6
  Top Signal w0.254: U1.6 43.168,8.4 43.412,8.645 45.553,8.645 45.702,8.496 45.702,7.049 45.838,6.913 46.607,6.913 U1.2 48.757,6.9 C47.2 48.557,6.4 U1.1 U1.1@46.607,6.413
  Top Signal w0.762: C47.2 48.907,6.875 48.951,6.919 48.951,8.044 v1(49.907,9)
NetC49_2: C49.2 P4.4 U2.1 U2.2 U2.5 U2.13 | length 11.4
  Top Signal w0.305: v1(62.7,5.8) 62.7,8.651 63.424,9.375 U2.5 ; U2.1 63.725,6.775 63.424,7.076 63.424,7.425 U2.2 67.025,7.425 C49.2@67.4,7.05
NetC55_2: C55.2 P5.2 U10.1 U10.2 U10.6 | length 13.5
  Top Signal w0.305: 45.8,84.5 46.3,85 47.76,85 47.973,84.787 48.287,84.787 48.5,84.575 48.5,82.911 48.898,82.513 49.501,82.513 U10.1 ; 47.76,85.06 47.76,87 P5.2 ; 48.5,83 U10.2
NetC56_2: C56.2 K1.4 R42.2 | length 16.8
  Top Signal w0.508: C56.2 19.75,36.94 R42.2 21.94,39.13 23.002,39.13 23.3,39.428 23.3,45.8 24.5,47 24.5,49.18 K1.4
NetD1_1: D1.1 R16.2 | length 1.8
  Top Signal w0.508: D1.1 R16.2
NetD2_1: D2.1 R20.2 | length 3
  Top Signal w0.508: R20.2 D2.1
NetD3_1: D3.1 R21.2 | length 3
  Top Signal w0.508: R21.2 D3.1
NetD4_1: D4.1 R22.2 | length 3.1
  Top Signal w0.508: R22.2 D4.1
NetD5_2: D5.2 K1.7 U13.6 | length 65.7
  Top Signal w0.254: v1(66.4,47.3) 69.349,47.3 69.949,47.9 U13.6
  Top Signal w0.762: D5.2 16.6,41.546 17.046,41.1 19.3,41.1 K1.7 v1(19.4,43.4) v1@19.316,43.484
  Bottom Signal w0.762: v1(19.4,43.4) 19.4,47.654 19.846,48.1 65.6,48.1 v1(66.4,47.3)
NetD6_2: D6.2 K1.12 U13.3 | length 61.3
  Top Signal w0.254: U13.3 72.851,48.9 73,49.049 73,49.651 73.149,49.8 v1(76.4,49.8)
  Top Signal w0.762: K1.12 v1@32.1,43.2 ; v1(32.1,43.4) 34.654,43.4 35.1,43.846 D6.2
  Bottom Signal w0.762: v1(32.1,43.4) 75,43.4 76.4,44.8 v1(76.4,49.8)
NetN2_2: N2.2 R2.2 R3.1 | length 15.5
  Top Signal w0.762: R3.1 37.1,26.971 37.249,27.12 N2.2 41.23,27.12 42.15,26.2 R2.2@42.15,18.6
NetN3_7: N3.7 R4.1 | length 12.3
  Top Signal w0.508: R4.1 53.65,24.6 55.625,22.625 N3.7
NetN3_9: N3.9 R9.2 R10.2 | length 3.9
  Top Signal w0.254: R10.2@69.671,18.121 N3.9 ; R10.2@70.15,18.149 R10.2@70.171,18.17
NetN3_11: N3.11 N4.6 R11.2 | length 81.2
  Top Signal w0.254: N3.11 73.175,23.275 R11.2 113.5,23.25 117.25,27 117.25,50.85 117.808,51.408 N4.6@125.228,51.408
NetN3_14: N3.14 N4.14 | length 99.5
  Top Signal w0.254: N3.14 69.696,25.25 72.141,25.25 72.245,25.146 74.155,25.146 74.259,25.25 112.5,25.25 115,27.75 115,69.75 117.002,71.752 N4.14@125.19,71.752
NetN4_2: N4.2 U1.3 U2.3 | length 105.6
  Top Signal w0.305: U1.3 47.507,7.4 48.107,8 48.107,10.2 48.807,10.9 v1(50.8,10.9) ; U2.3 67.475,8.075 68.3,8.9 v1(68.3,12)
  Bottom Signal w0.508: v1@50.837,10.9 51.937,12 v1(68.3,12) 75.4,12 84,20.6 99.6,20.6 108.4,29.4 108.4,37.2 112.472,41.272 N4.2@125.44,41.272
  Bottom Signal w0.762: v1(50.8,10.9) v1@50.837,10.9
NetN4_3: N4.3 U10.3 | length 117
  Top Signal w0.305: U10.3 50.6,83.5 50.8,83.3 50.8,80.9 51.6,80.1 v1(54.1,80.1)
  Bottom Signal w0.305: v1(54.1,80.1) 77.2,80.1 77.7,79.6 77.7,61 80.677,58.023 106.377,58.023 107.294,57.106 107.294,49.868 106.7,49.274 106.7,41.279 106.879,41.1 110.3,41.1 113.012,43.812 N4.3@125.44,43.812
NetN4_4: N4.4 U12.5 | length 47.1
  Top Signal w0.508: U12.5 131.902,6.525 132.4,7.023 132.4,17.113 132.1,17.413 v1(132.1,17.6)
  Bottom Signal w0.508: N4.4@125.478,46.328 125.505,46.3 127.1,46.3 128.2,45.2 128.2,21.5 v1(132.1,17.6)
NetN4_5: N4.5 R13.2 U3.13 | length 79.4
  Top Signal w0.254: U3.13 56.525,62.975 R13.2 57,63 77.9,63 89.9,51 100.3,51 101.244,50.056 111.556,50.056 v1(111.75,50.25)
  Bottom Signal w0.254: v1(111.75,50.25) 113.111,48.889 N4.5@125.228,48.889
NetN4_9: N4.9 R20.1 | length 12.5
  Top Signal w0.508: N4.9 R20.1@138.048,59.102
NetN4_10: N4.10 R21.1 | length 12.5
  Top Signal w0.508: N4.10 R21.1@138.042,61.642
NetN4_11: N4.11 R22.1 | length 12.5
  Top Signal w0.508: N4.11@125.583,64.2 R22.1
NetN4_13: N4.13 R10.1 | length 99.7
  Top Signal w0.254: R10.1 77.85,18.1 82.25,22.5 113.75,22.5 126.75,35.5 126.75,57.5 126.5,57.75 124,57.75 123.5,58.25 123.5,69 123.712,69.212 N4.13@125.19,69.212
NetN4_17: N4.17 R16.1 | length 17.1
  Top Signal w0.508: R16.1 108.6,40.1 109.1,40.6 109.1,43.54 108.802,43.838 N4.17@105.578,43.838
NetN4_21: N4.21 R39.2 U9.2 | length 19.4
  Top Signal w0.254: U9.2 R39.2@97.63,55.52
  Bottom Signal w0.254: U9.2 99.52,55.52 101.616,57.616 106.06,57.616 106.3,57.376 106.3,55.402 N4.21@104.87,53.972
NetN4_25: N4.25 R12.2 U3.15 | length 71.1
  Top Signal w0.254: U3.15 54.15,64.275 ; R12.2 54.15,64.275 ; N4.25@104.87,64.132 101.132,64.132 100.25,63.25 100.25,53.15 99.5,52.4 90.4,52.4 78.525,64.275 54.15,64.275
NetN4_26: N4.26 U3.10 | length 96.9
  Top Signal w0.254: U3.10 53.516,61.025 53.991,61.5 77.3,61.5 89.3,49.5 99.5,49.5 104,45 112.25,45 113,45.75 113,66 112.328,66.672 N4.26@104.87,66.672
NetP2_1: P2.1 R33.2 | length 4.4
  Top Signal w0.762: P2.1 R33.2
NetP3_1: P3.1 R36.2 | length 4.2
  Top Signal w0.762: P3.1 R36.2
NetP6_1: P6.1 P6.8 R23.1 | length 24.1
  Top Signal w0.508: P6.8 98.203,7.505 97.905,7.803 97.905,14.907 98.203,15.205 P6.1 109.505,15.205 110.4,16.1 R23.1@112.25,16.1
NetP7_6: P7.6 R44.2 | length 61.5
  Top Signal w0.762: R44.2 68.7,45.65 68.869,45.481 68.869,45.181 72.05,42 83.1,42 91,34.1 91,29 93.4,26.6 v1(107.6,26.6)
  Bottom Signal w0.762: v1(107.6,26.6) 113.2,26.6 113.98,25.82 P7.6
NetP7_8: P7.8 R43.2 | length 58.7
  Top Signal w0.762: R43.2 74.5,44 75.4,43.1 83.6,43.1 92.2,34.5 92.2,29.4 93.8,27.8 v1(109.5,27.8)
  Bottom Signal w0.762: v1(109.5,27.8) 109.597,27.703 114.297,27.703 116.52,25.48 P7.8
NetP7_12: P7.12 U11.5 | length 26.2
  Top Signal w0.508: v1(136.3,9.2) 137.555,9.2 137.925,8.83 U11.5
  Bottom Signal w0.508: P7.12 125.96,21.24 128.6,18.6 128.6,13.5 130.2,11.9 135.5,11.9 136.3,11.1 v1(136.3,9.2)
NetR6_1: R6.1 U1.5 | length 2.8
  Top Signal w0.305: U1.5 47.328,8.4 47.507,8.579 47.507,9.652 47.109,10.05 R6.1
NetR7_1: R7.1 U2.6 | length 1.9
  Top Signal w0.254: U2.6 64.909,10 R7.1
NetR14_1: R14.1 U3.9 | length 2.6
  Top Signal w0.254: R14.1@54.125,60.625 R14.1
  Top Signal w0.508: U3.9 R14.1@54.125,60.375
NetR15_1: R15.1 U3.16 | length 2
  Top Signal w0.254: R15.1@52.075,66.875 R15.1
  Top Signal w0.508: U3.16 R15.1@52.075,66.875
NetR25_2: R25.2 U4.3 | length 5.2
  Top Signal w0.508: R25.2 134.297,38.447 134.297,39.515 134.398,39.615 U4.3
NetR26_2: R26.2 U4.7 | length 2.2
  Top Signal w0.508: U4.7 143.821,40.885 143.846,40.86 143.846,40.573 144.136,40.283 145.117,40.283 R26.2
NetR28_2: R28.2 U5.3 | length 5.1
  Top Signal w0.508: R28.2 134.372,27.772 134.372,28.69 134.548,28.865 U5.3
NetR29_2: R29.2 U5.7 | length 2.4
  Top Signal w0.508: U5.7 143.447,30.11 143.846,30.11 143.846,29.823 144.144,29.525 145.375,29.525 R29.2
NetR31_2: R31.2 U6.3 | length 5.8
  Top Signal w0.508: R31.2 134,47.65 134,49.067 134.298,49.365 U6.3
NetR32_2: R32.2 U6.7 | length 2.2
  Top Signal w0.508: U6.7 143.821,50.635 143.846,50.61 143.846,50.323 144.136,50.033 145.117,50.033 R32.2
NetR33_1: R33.1 Rf1.2 U7.1 | length 8.4
  Top Signal w0.254: R33.1 R33.1@19.15,61.85 ; U7.1 U7.1@24.4,61.865
  Top Signal w0.508: R33.1@19.15,61.85 U7.1 ; U7.1@24.4,61.865 Rf1.2
NetR34_1: R34.1 U3.7 | length 24.6
  Top Signal w0.508: R34.1 29.902,55.15 30.2,55.448 30.2,60.3 30.925,61.025 U3.7
NetR35_2: R35.2 Rf1.1 U7.4 | length 7.7
  Top Signal w0.254: Rf1.1 R35.2
  Top Signal w0.508: Rf1.1 26.944,64.744 26.944,63.594 26,62.65 26,60.548 26.598,59.95 U7.4
NetR36_1: R36.1 Rf2.2 U8.1 | length 8.3
  Top Signal w0.254: U8.1@24.335,85.05 U8.1@24.4,85.115
  Top Signal w0.508: R36.1 18.9,85 U8.1 ; U8.1@24.4,85.115 Rf2.2
NetR37_1: R37.1 U3.3 | length 32.8
  Top Signal w0.508: R37.1 28.85,78.05 30.25,76.65 30.25,63.923 30.548,63.625 U3.3
NetR38_2: R38.2 Rf2.1 U8.4 | length 8.1
  Top Signal w0.254: Rf2.1@27,87.7 Rf2.1
  Top Signal w0.508: Rf2.1@27,87.7 27,86.3 25.901,85.201 25.901,83.249 26.05,83.1 U8.4 ; Rf2.1 R38.2
NetR41_1: R41.1 U10.5 | length 2.3
  Top Signal w0.305: U10.5 R41.1
NetR43_1: R43.1 R46.1 U13.2 | length 5
  Top Signal w0.254: U13.2 74.35,48.4 R43.1@74.4,48.45
  Top Signal w0.508: R43.1 74.564,48.386 74.564,47.498 74.862,47.2 R46.1
NetR44_1: R44.1 R45.1 U13.5 | length 5.4
  Top Signal w0.254: R44.1@68.4,48.45 68.45,48.4 U13.5
  Top Signal w0.508: R45.1 68.102,49.7 68.4,49.402 R44.1@68.4,48.45
pos_out: C4.2 C5.2 C6.2 C37.2 C38.2 C39.2 C40.2 C46.1 C48.2 N1.4 N2.4 U1.9 U1.10 U7.2 U8.2 | length 27.7
  Top Signal w0.254: C46.1 19.9,21.9 C46.1@19.95,21.95 ; v1(22.5,60.65) 22.775,60.65 23.025,60.9 U7.2 ; v1(22.5,83.8) 22.775,83.8 v1@23.025,84.05 ; N1.4@24.35,21.95 N1.4 ; C6.2 38.057,6.4 41.107,6.4 ; N2.4@39.6,21.95 N2.4 ; C48.2 41.107,4.65 41.107,6.4 ; U1.10 41.107,6.4 ; U1.9 41.255,6.9 41.107,6.751 41.107,6.4
  Top Signal w0.508: C46.1 19.95,21.95 C4.2 N1.4@24.35,21.95 ; v1@23.025,84.05 U8.2 ; C5.2 N2.4@39.6,21.95
  Top Signal w0.762: C37.2@20,58.55 C38.2 22.331,58.55 22.5,58.719 v1(22.5,60.65) ; C40.2 C39.2 22.331,81.9 22.5,82.069 v1(22.5,83.8)
  other v1: 40.007,6.4
ref_buff_dac: C17.2 R35.1 R38.1 U3.1 | length 41.7
  Top Signal w0.508: C17.2@42.25,64.925 U3.1
  Top Signal w0.762: R35.1@31.375,64.925 36,64.925 ; R38.1 34.95,87.8 36,86.75 36,64.925 ; C17.2@42.25,64.925 36,64.925
REFCAP: C10.2 N3.6 | length 5.1
  Top Signal w0.254: C10.2@59,23.9 59.625,23.275 N3.6
REFIO: C11.2 C12.2 N3.4 N3.15 | length 14.4
  Top Signal w0.508: N3.4 67.325,24.575 67.75,25 67.75,25.875 ; N3.15 67.75,25.875 ; C12.2 C11.2 69.85,27.649 69.701,27.5 67.899,27.5 67.75,27.351 67.75,25.875
SPI1_CS_SRAM1: N4.24 R24.2 U4.1 | length 52.5
  Top Signal w0.508: R24.2@133.4,42.25 135.25,42.25 135.345,42.155 U4.1
  Bottom Signal w0.508: N4.24@105.295,61.592 121.658,61.592 122.85,60.4 133.6,60.4 135.325,58.675 v1(135.325,42.175)
SPI1_CS_SRAM2: N4.23 R27.2 U5.1 | length 61.5
  Top Signal w0.508: R27.2 133.249,33.351 133.249,31.449 v1(133.2,31.4) 133.205,31.405 U5.1
  Bottom Signal w0.508: N4.23@105.295,59.052 123.198,59.052 124.35,57.9 132.35,57.9 133.25,57 133.25,31.45 v1(133.2,31.4)
SPI1_CS_SRAM3: N4.28 R30.2 U6.1 | length 51.4
  Top Signal w0.508: R30.2 v1(136.306,52) ; v1@136.306,51.905 U6.1
  Bottom Signal w0.508: N4.28@105.295,71.752 118.498,71.752 122.5,67.75 122.5,63.75 123.35,62.9 135.1,62.9 136.306,61.694 v1(136.306,52)
SPI1_MISO: N3.13 N4.8 U3.8 | length 190.2
  Top Signal w0.254: U3.8 49.025,60.375 49.75,59.65 49.75,56.799 49.899,56.65 58.25,56.65 58.609,57.009 62.3,60.7 77,60.7 88.95,48.75 98.25,48.75 104.5,42.5 v1(107.7,42.5) ; N3.13 112.825,24.575 115.75,27.5 115.75,55.75 116.512,56.512 N4.8@125.19,56.512
  Bottom Signal w0.254: v1(107.7,42.5) 107.7,55.95 108.262,56.512 N4.8@125.19,56.512
SPI1_MOSI: N3.10 N4.22 U3.14 | length 130.9
  Top Signal w0.254: U3.14 52.1,63.6 78.2,63.6 90.1,51.7 100.4,51.7 101,52.3 101,54.75 102.762,56.512 N4.22@105.195,56.512 ; N3.10 70.955,22.625 71.103,22.476 71.103,21.899 71.252,21.75 v1(79.25,21.75)
  Bottom Signal w0.254: v1(79.25,21.75) 100,21.75 101,22.75 101,54.75 102.762,56.512 N4.22@105.195,56.512
SPI1_SCK: N3.12 N4.7 U3.12 | length 168.8
  Top Signal w0.254: U3.12 55.416,62.325 55.795,61.946 57.705,61.946 58.059,62.3 77.5,62.3 89.55,50.25 100.25,50.25 102.75,47.75 v1(109,47.75) ; N3.12 72.116,23.925 72.245,24.054 74.155,24.054 74.284,23.925 113.175,23.925 116.5,27.25 116.5,53.25 117.25,54 125.162,54 N4.7@125.19,53.972
  Bottom Signal w0.254: v1(109,47.75) 109,53.601 109.399,54 125.162,54 N4.7@125.19,53.972
SPI1_SRAM_MISO: P6.3 P7.7 R18.2 U4.2 U5.2 U6.2 | length 81.6
  Top Signal w0.508: P6.3 110.395,13.005 110.7,12.7 110.7,11.298 110.998,11 R18.2 v1(113.6,11) ; P7.7 117.8,19.98 117.8,22.997 118.553,23.75 139.202,23.75 139.5,24.048 139.5,41 ; U5.2 139.135,30.135 ; U4.2 139.385,40.885 139.5,41 ; U6.2 139.202,50.635 139.5,50.337 139.5,41
  Bottom Signal w0.508: v1(113.6,11) 114.9,12.3 114.9,17.08 P7.7
SPI1_SRAM_MOSI: P6.7 P7.9 R17.2 U4.5 U5.5 U6.5 | length 88.3
  Top Signal w0.508: P6.7 101.395,8.605 101.681,8.319 110.417,8.319 111.098,9 R17.2@112.25,9 ; v1@112.247,7.047 112.247,8.897 R17.2 ; P7.9 120.36,20 141.702,20 142,20.298 142,27.5 ; U5.5 142.095,27.595 142,27.5 ; U4.5 142.155,38.345 142,38.5 ; U6.5 142.298,48.095 142,47.797 142,38.5 ; 142,27.5 142,38.5
  Bottom Signal w0.508: v1@112.2,7.1 118.4,7.1 119.06,7.76 P7.9
  other v1: 112.2,7
SPI1_SRAM_SCK: P6.5 P7.5 U4.6 U5.6 U6.6 | length 91.4
  Top Signal w0.508: P6.5@99.598,10.805 v1@102.395,10.805 ; v1(126.2,18.9) 144.102,18.9 146.75,21.548 146.75,28.25 ; U5.6 143.821,28.865 143.846,28.84 143.846,28.798 144.375,28.269 146.731,28.269 146.75,28.25 ; U4.6 143.447,39.59 143.846,39.59 144.436,39 146.75,39 ; U6.6 143.447,49.34 143.846,49.34 144.686,48.5 146.25,48.5 146.75,48 146.75,39 ; 146.75,28.25 146.75,39
  Bottom Signal w0.508: v1(102.4,10.8) 103.8,10.8 108.5,15.5 113,15.5 113.98,16.48 P7.5 ; P7.5@113.969,18.689 115.28,20 125.1,20 v1(126.2,18.9)
SPI2_NSS: P6.2 P7.11 R19.2 | length 27.8
  Top Signal w0.508: P6.2@99.903,14.1 R19.2 112.546,13.804 112.546,13.498 113.175,12.869 120.971,12.869 121.6,13.498 P7.11
TIA_out: K1.3 K1.10 N1.6 R3.2 | length 30.8
  Top Signal w0.508: R3.2@34.38,24.58 R3.2
  Top Signal w0.762: K1.3 K1.10 27.02,26.58 28.3,25.3 29.02,24.58 N1.6 R3.2@34.38,24.58
pads on no net: N1.1 N1.5 N1.8 N2.1 N2.5 N2.8 N4.1 N4.12 N4.15 N4.16 N4.19 N4.20 N4.27 P6.G1 P6.G2 P6.G3 P6.G4 P7.10 U1.4 U2.4 U2.7 U3.2 U3.6 U10.4 U11.3 U11.7 U12.3 U12.7

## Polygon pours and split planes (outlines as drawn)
GND on GND "GND_L02_P000" (solid, pour order 0): 0,100 0,0 160,0 160,100
DVDD on Power Plane "DVDD_L03_P007" (solid, pour order 7): 125.6,9.7 125.8,9.5 142.2,9.5 142.4,9.3 142.4,0 160,0 160,100 65.25,100 65.25,80.75 64.75,80.25 51.25,80.25 50.75,79.75 50.75,44.75 51.25,44.25 66.75,44.25 68.25,42.75 68.25,11 68.75,10.5 81.5,10.5 81.75,10.25 81.75,0 99.1,0 99.1,15.8 99.6,16.3 125.106,16.3 125.6,15.806
NetC33_2 on Power Plane "NONET_L-01_P-001" (solid, pour order 17): 142.2,9.5 142.4,9.3 142.4,0 125.6,0 125.6,9.5
DVDD_SD on Power Plane "NONET_L-01_P-001" (solid, pour order 15): 99.6,16.3 99.1,15.8 99.1,0 125.6,0 125.6,16 125.3,16.3
AVDD on Power Plane "AVDD_L03_P008" (solid, pour order 8): 26,88.9 36.8,88.9 37.5,88.2 37.5,38.4 53.5,38.4 53.5,20 54,19.5 60.25,19.5 61,18.75 61,10.5 67.75,10.5 68,10.75 68,42.75 66.75,44 51.25,44 50.5,44.75 50.5,79.75 51.25,80.5 64.5,80.5 65,81 65,100 25.5,100 26,99.5
NetC49_2 on Power Plane "NETC49_2_L03_P005" (solid, pour order 5): 75.75,4.75 75.75,0 81.5,0 81.5,10.25 61.25,10.25 61,10 61,4.75 61.25,4.5 70,4.5 70.25,4.75 70.25,7 70.5,7.25 75.5,7.25 75.75,7
NetC47_2 on Power Plane "NETC47_2_L03_P004" (solid, pour order 4): 70.5,7 75.5,7 75.5,0 48.25,0 47.75,0.5 47.75,10.5 48,10.75 54.5,10.75 54.75,10.5 54.75,5 55.5,4.25 70,4.25 70.5,4.75
neg_out on Power Plane "NEG_OUT_L03_P003" (solid, pour order 3): 60.25,19.25 54,19.25 53.25,20 53.25,38.2 37.25,38.2 37.25,88.15 36.7,88.7 26,88.7 26,41.75 26.25,41.5 28.5,41.5 29.25,40.75 29.25,23.3 43,23.3 43,11.25 43.25,11 54.75,11 55,10.75 55,5 55.5,4.5 60.5,4.5 60.75,4.75 60.75,18.75
pos_out on Power Plane "POS_OUT_L03_P002" (solid, pour order 2): 15,24 15.4,24.4 15.5,24.4 15.5,29.5 15.8,29.8 25.6,29.8 26,30.2 26,34.6 15.25,34.6 15.25,83.25 14.75,83.75 0,83.75 0,100 25.25,100 25.75,99.5 25.75,41.75 26.25,41.25 28.5,41.25 29,40.75 29,23.1 42.75,23.1 42.75,11.25 43.25,10.75 47.25,10.75 47.5,10.5 47.5,0.5 47,0 0,0 0,24
no net on Top Paste "NONET_L03_P-001" (solid): 101.475,19.6 101.475,18.15 103.475,18.15 103.475,19.6
no net on Top Paste "NONET_L03_P-001" (solid): 93.196,19.617 93.196,18.167 95.196,18.167 95.196,19.617
no net on Top Paste "NONET_L03_P-001" (solid): 101.5,5.85 101.5,4.4 103.5,4.4 103.5,5.85
no net on Top Paste "NONET_L03_P-001" (solid): 93.2,5.85 93.2,4.4 95.2,4.4 95.2,5.85
no net on Top Paste "NONET_L03_P-001" (solid): 101.5,19.6 101.5,18.15 103.5,18.15 103.5,19.6
no net on Top Paste "NONET_L03_P-001" (solid): 93.2,19.6 93.2,18.15 95.2,18.15 95.2,19.6
GND on Top Signal "GND_L01_P010" (solid, pour order 10): 160,3 160,0 0,0 0,3
GND on Top Signal "GND_L01_P009" (solid, pour order 9): 0,100 0,97 160,97 160,100
no net on Top Overlay "NONET_L-01_P-001" (solid, pour order 18): 69.016,87.9 84.016,87.9 77.016,74.9
no net on Top Solder (solid): 10.6,26.2 11.1,25.7 25.3,25.7 25.8,26.2 25.8,28 25.3,28.5 18.6,28.5 18.1,29 18.1,38.6 17.6,39.1 16.4,39.1 15.9,38.6 15.9,29 15.4,28.5 11.1,28.5 10.6,28
no net on Top Solder "NONET_L03_P-001" (solid): 101.5,5.875 101.5,4.425 103.5,4.425 103.5,5.875
no net on Top Solder "NONET_L03_P-001" (solid): 93.2,5.85 93.2,4.4 95.2,4.4 95.2,5.85
no net on Top Solder "NONET_L03_P-001" (solid): 101.5,19.6 101.5,18.15 103.5,18.15 103.5,19.6
no net on Top Solder "NONET_L03_P-001" (solid): 93.196,19.617 93.196,18.167 95.196,18.167 95.196,19.617
no net on Top Solder "NONET_L03_P-001" (solid): 160,100 160,97 0,97 0,100
no net on Top Solder "NONET_L03_P-001" (solid): 0,3 0,0 160,0 160,3
GND on Bottom Signal "GND_L04_P011" (solid, pour order 11): 160,100 160,97 0,97 0,100
GND on Bottom Signal "GND_L04_P006" (solid, pour order 6): 160,3 160,0 0,0 0,3
no net on Bottom Solder "NONET_L03_P-001" (solid): 0,100 0,97 160,97 160,100
no net on Bottom Solder "NONET_L03_P-001" (solid): 0,3 0,0 160,0 160,3

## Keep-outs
Keep-Out Layer:
  region: 0,3 0,0 160,0 160,3
  region: 0,100 0,97 160,97 160,100

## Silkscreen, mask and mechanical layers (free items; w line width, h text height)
Top Overlay:
  pour cut-out: 71,84.5 82.5,84.5 82.5,81.7 71,81.7
  text "Drain Source" at 0.703,93.703 h1.52
  text "TIA Current Messurment Unit" at 56.8,88.5 h1.52
  text "VISHAY." at 71,81.9 h2
  text "Thanks for sponsoring" at 61.503,73.211 h1.52
  text "Gate Source" at 0.703,70.103 h1.52
  text "S_TIA" at 0.703,35.457 h1.52
  text "I have no idea / what I'm  / doing. -RESI" at 0.4,11.1 h1.2
Top Paste:
  lines w0.254: 105.2,22.5 107.6,22.5
Mechanical 1:
  the board outline again, w0.254
Drill Drawing:
  circle w0.203: c165.476,82.547 r0.847
  lines w0.203: 164.63,74.503 165.053,74.503 165.476,74.08 165.9,74.503 166.323,74.503 165.9,74.927 166.323,75.35 165.9,75.35 165.476,75.773 165.053,75.35 164.63,75.35 165.053,74.927 164.63,74.503 ; 164.63,77.89 165.476,78.313 166.323,77.89 165.9,78.737 166.323,79.583 165.476,79.16 164.63,79.583 165.053,78.737 164.63,77.89 ; 164.63,85.933 165.053,85.933 165.053,85.51 165.9,85.51 165.9,85.933 166.323,85.933 166.323,86.78 165.9,86.78 165.9,87.203 165.053,87.203 165.053,86.78 164.63,86.78 164.63,85.933 ; 164.63,90.167 165.476,89.32 166.323,90.167 165.476,91.013 164.63,90.167 ; 164.63,94.823 166.323,94.823 165.476,93.13 164.63,94.823
  lines w0.254: 163.127,72.937 307.319,72.937 ; 163.127,95.797 307.319,95.797 ; 176.957,69.127 176.957,99.607 ; 191.837,69.127 191.837,99.607 ; 220.175,69.127 220.175,99.607 ; 232.862,69.127 232.862,99.607 ; 251.338,69.127 251.338,99.607 ; 291.356,69.127 291.356,99.607 ; 163.127,69.127 307.319,69.127 307.319,99.607 163.127,99.607 163.127,69.127
  text "Symbol" at 165.413,96.94 h1.83
  text "Count" at 178.1,96.94 h1.83
  text "Hole Size" at 192.98,96.94 h1.83
  text "Plated" at 221.318,96.94 h1.83
  text "Hole Type" at 234.005,96.94 h1.83
  text "Drill Layer Pair" at 252.481,96.94 h1.83
  text "Via/Pad" at 292.499,96.94 h1.83
  text "114" at 178.1,93.13 h1.52
  text "0,600mm (23,62mil)" at 192.98,93.13 h1.52
  text "PTH" at 221.318,93.13 h1.52
  text "Round" at 234.005,93.13 h1.52
  text "Top Signal - Bottom Signal" at 252.481,93.13 h1.52
  text "Via" at 292.499,93.13 h1.52
  text "2" at 178.1,89.32 h1.52
  text "0,700mm (27,56mil)" at 192.98,89.32 h1.52
  text "PTH" at 221.318,89.32 h1.52
  text "Round" at 234.005,89.32 h1.52
  text "Top Signal - Bottom Signal" at 252.481,89.32 h1.52
  text "Pad" at 292.499,89.32 h1.52
  text "5" at 178.1,85.51 h1.52
  text "0,800mm (31,50mil)" at 192.98,85.51 h1.52
  text "PTH" at 221.318,85.51 h1.52
  text "Round" at 234.005,85.51 h1.52
  text "Top Signal - Bottom Signal" at 252.481,85.51 h1.52
  text "Pad" at 292.499,85.51 h1.52
  text "42" at 178.1,81.7 h1.52
  text "0,900mm (35,43mil)" at 192.98,81.7 h1.52
  text "PTH" at 221.318,81.7 h1.52
  text "Round" at 234.005,81.7 h1.52
  text "Top Signal - Bottom Signal" at 252.481,81.7 h1.52
  text "Pad" at 292.499,81.7 h1.52
  text "28" at 178.1,77.89 h1.52
  text "1,000mm (39,37mil)" at 192.98,77.89 h1.52
  text "PTH" at 221.318,77.89 h1.52
  text "Round" at 234.005,77.89 h1.52
  text "Top Signal - Bottom Signal" at 252.481,77.89 h1.52
  text "Pad" at 292.499,77.89 h1.52
  text "6" at 178.1,74.08 h1.52
  text "2,000mm (78,74mil)" at 192.98,74.08 h1.52
  text "PTH" at 221.318,74.08 h1.52
  text "Round" at 234.005,74.08 h1.52
  text "Top Signal - Bottom Signal" at 252.481,74.08 h1.52
  text "Pad" at 292.499,74.08 h1.52
  text "197 Total" at 178.1,70.27 h1.52

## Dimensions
0,0 to 0,62 on Mechanical 1
0,0 to 0,27 on Mechanical 1
0,0 to 0,85 on Mechanical 1
0,97 to 0,100 on Mechanical 1
0,3 to 0,0 on Mechanical 1
0,0 to 0,100 on Mechanical 1
0,0 to 160,0 on Mechanical 1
